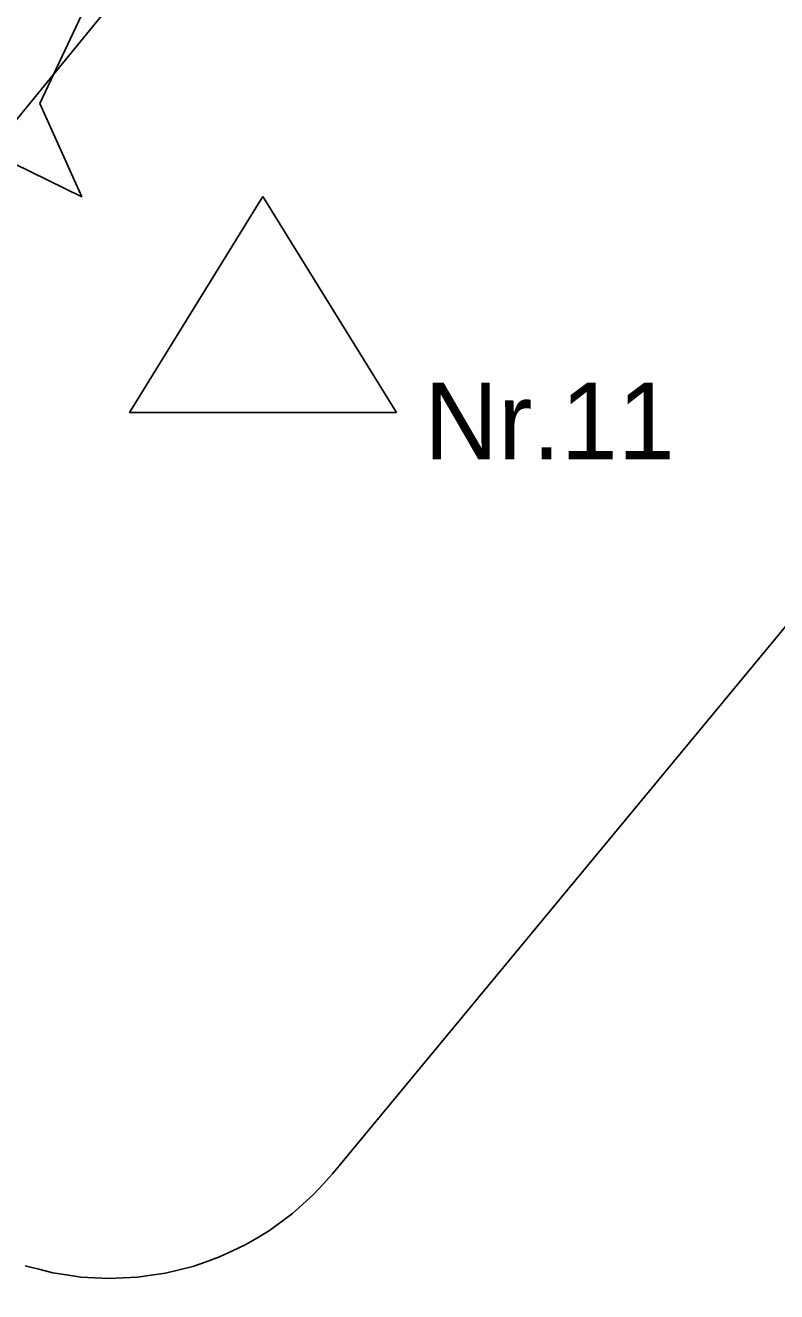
# Model space of a CAD drawing. Extents: x 468834 to 503362, y 294936 to 320859.
# Drawn here: x 473819.1 to 474079.3, y 307868.5 to 308306.7 of the extents above; entities that cross this region are included whole.
import ezdxf

# ---------------------------------------------------------------- set-up
doc = ezdxf.new("R2010")
doc.units = 0
for name, color, linetype in [('7311080102_vides un dabas resursu aizsardzības aizsargjoslas teritorija ap purvu ar platību lielāku par 100 hektāriem', 7, 'Continuous'), ('7313020300_nacionālā parka dabas lieguma zonas teritorija', 7, 'Continuous'), ('7313020500_nacionālā parka ainavu aizsardzības zonas teritorija', 7, 'Continuous'), ('7316060100_sanitārās aizsargjoslas teritorija ap atkritumu apglabāšanas poligonu', 7, 'Continuous'), ('Piesārņota vieta', 7, 'Continuous'), ('Teksts', 7, 'Continuous')]:
    doc.layers.add(name, color=color, linetype=linetype)

msp = doc.modelspace()

# ---------------------------------------------------------------- linework, layer by layer
at = {"layer": '7311080102_vides un dabas resursu aizsardzības aizsargjoslas teritorija ap purvu ar platību lielāku par 100 hektāriem'}
for p, q in [((473891.95, 308424.11), (473824.22, 308279.64)), ((473838.76, 308247.37), (473719.93, 308305.57)), ((473824.22, 308279.64), (473838.76, 308247.37))]:
    msp.add_line(p, q, dxfattribs=at)
at = {"layer": '7313020300_nacionālā parka dabas lieguma zonas teritorija'}
msp.add_lwpolyline([(473153.56, 307465), (473960.88, 308451.05)], dxfattribs=at)
at = {"layer": '7313020500_nacionālā parka ainavu aizsardzības zonas teritorija'}
msp.add_lwpolyline([(474045.29, 308536.11), (474045.94, 308532.47), (474058.16, 308456.26), (473960.88, 308451.05), (473153.56, 307465)], dxfattribs=at)
at = {"layer": '7316060100_sanitārās aizsargjoslas teritorija ap atkritumu apglabāšanas poligonu'}
msp.add_lwpolyline([(474167.75, 308201.81), (473925.5, 307909.29), (473922.22, 307905.7), (473918.94, 307902.11), (473915.26, 307898.8), (473911.64, 307895.55), (473907.66, 307892.61), (473903.74, 307889.73), (473899.49, 307887.2), (473895.3, 307884.71), (473890.82, 307882.61), (473886.42, 307880.55), (473881.75, 307878.9), (473877.17, 307877.28), (473872.36, 307876.09), (473867.64, 307874.93), (473862.74, 307874.22), (473857.93, 307873.52), (473852.98, 307873.3), (473848.12, 307873.08), (473843.18, 307873.34), (473838.32, 307873.59), (473833.43, 307874.34), (473828.62, 307875.07), (473823.82, 307876.29), (473819.11, 307877.49)], dxfattribs=at)
at = {"layer": 'Piesārņota vieta'}
for p, q in [((473901.41, 308247.5), (473855.16, 308172.77)), ((473947.66, 308172.77), (473901.41, 308247.5)), ((473855.16, 308172.77), (473947.66, 308172.77))]:
    msp.add_line(p, q, dxfattribs=at)

# ---------------------------------------------------------------- texts
at = {"layer": 'Teksts'}
msp.add_text('Nr.11', height=26.542, dxfattribs=at).set_placement((473957.21, 308156.56))

doc.saveas('drawing.dxf')
